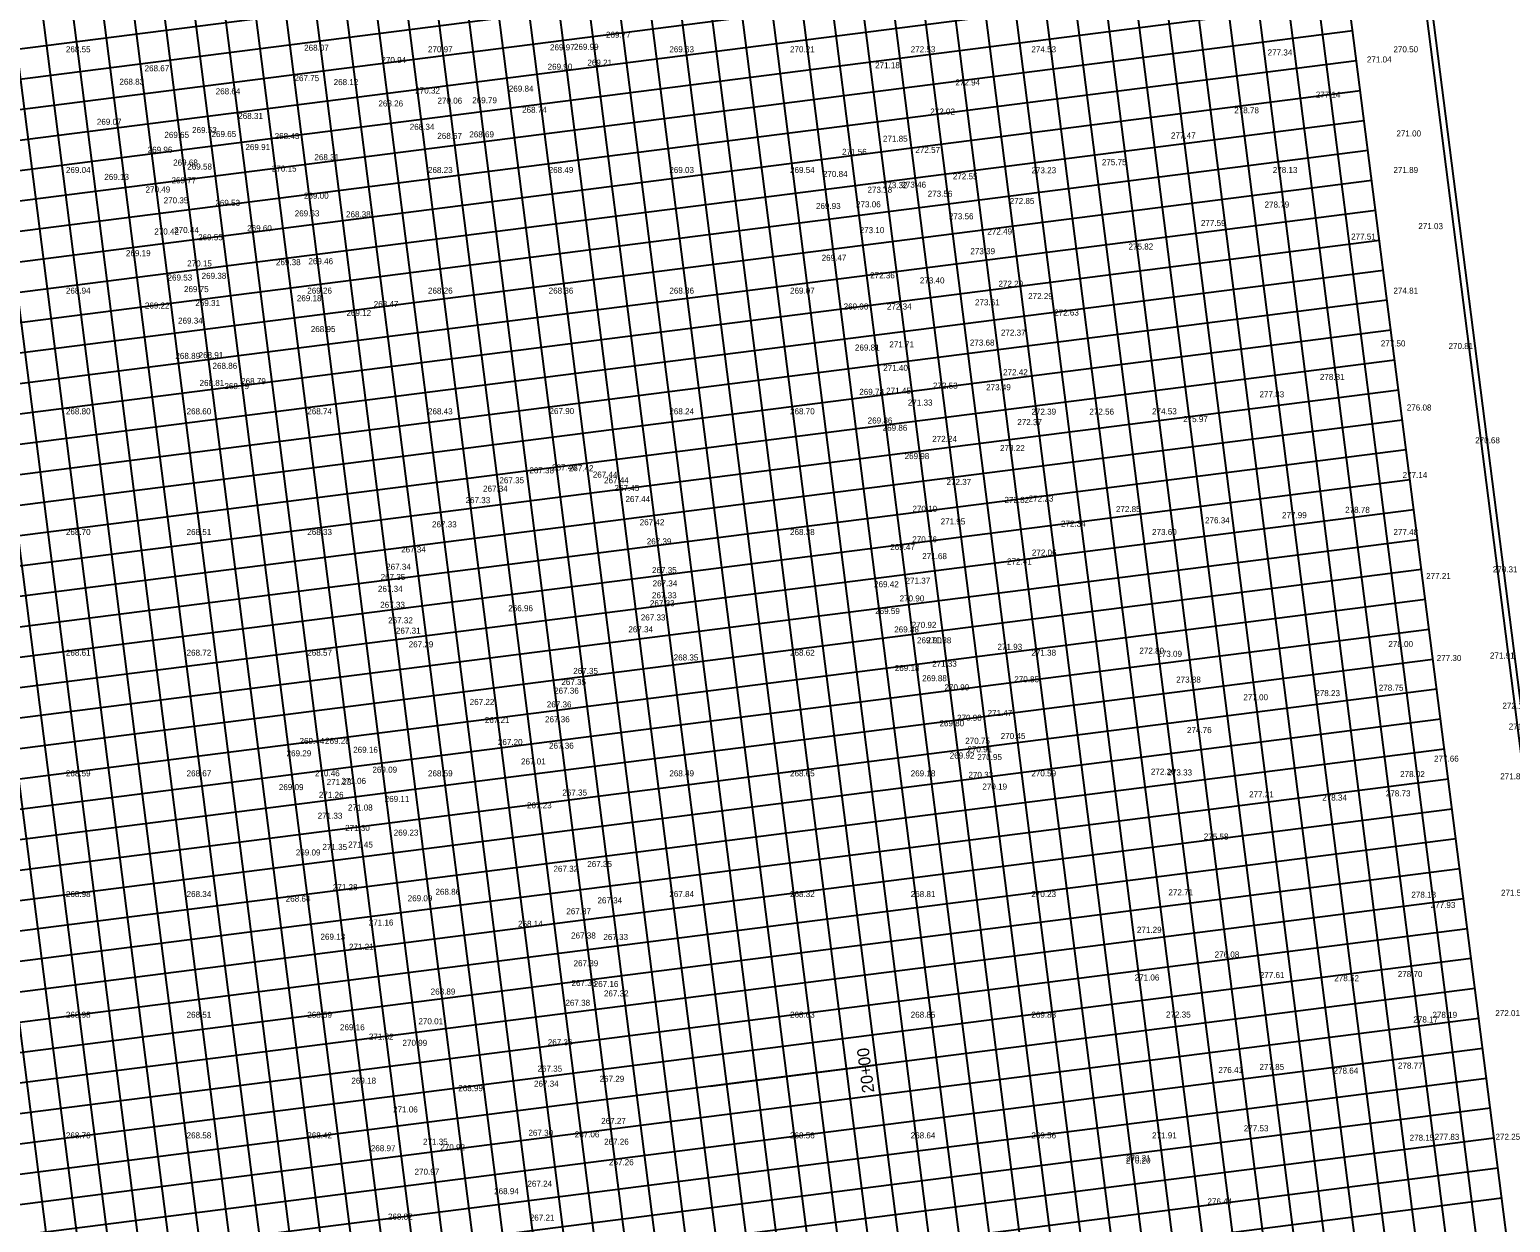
# Model space of a CAD drawing. Extents: x 2166991 to 2168450, y 842134 to 844444.
# Drawn here: x 2167887.5 to 2168132.8, y 843607.1 to 843804.8 of the extents above; entities that cross this region are included whole.
import ezdxf

# ---------------------------------------------------------------- set-up
doc = ezdxf.new("R2010")
doc.units = 0
for name, color, linetype in [('Exist Plan Preparation Drainage Notes Label', 7, 'Continuous'), ('Prop Drainage Structure Pipe Alternate 18in Label', 7, 'Continuous'), ('Prop Plan Preparation Watershed Post Construction', 7, 'Continuous'), ('Scratch_Level_3', 7, 'Continuous')]:
    doc.layers.add(name, color=color, linetype=linetype)

msp = doc.modelspace()

# ---------------------------------------------------------------- linework, layer by layer
at = {"layer": 'Exist Plan Preparation Drainage Notes Label'}
for p, q in [((2168231.53, 842827.51), (2168073.16, 844067.43)), ((2168181.94, 842821.17), (2168023.56, 844061.1)), ((2168132.34, 842814.84), (2167973.96, 844054.76)), ((2168082.74, 842808.5), (2167924.37, 844048.43)), ((2168033.15, 842802.17), (2167874.77, 844042.09)), ((2168208.53, 842849.77), (2168056.49, 844040.1)), ((2168213.49, 842850.4), (2168061.45, 844040.73)), ((2168218.45, 842851.04), (2168066.41, 844041.37)), ((2168223.41, 842851.67), (2168071.37, 844042)), ((2168188.69, 842847.24), (2168036.65, 844037.57)), ((2168193.65, 842847.87), (2168041.61, 844038.2)), ((2168198.61, 842848.5), (2168046.57, 844038.83)), ((2168203.57, 842849.14), (2168051.53, 844039.47)), ((2168168.85, 842844.7), (2168016.81, 844035.03)), ((2168173.81, 842845.34), (2168021.77, 844035.67)), ((2168183.73, 842846.6), (2168031.69, 844036.93)), ((2168149.01, 842842.17), (2167996.97, 844032.5)), ((2168153.97, 842842.8), (2168001.93, 844033.13)), ((2168158.93, 842843.44), (2168006.89, 844033.77)), ((2168163.89, 842844.07), (2168011.85, 844034.4)), ((2168134.13, 842840.27), (2167982.09, 844030.6)), ((2168139.09, 842840.9), (2167987.05, 844031.23)), ((2168144.05, 842841.54), (2167992.01, 844031.86)), ((2168114.29, 842837.73), (2167962.25, 844028.06)), ((2168119.25, 842838.37), (2167967.21, 844028.7)), ((2168124.21, 842839), (2167972.17, 844029.33)), ((2168094.45, 842835.2), (2167942.41, 844025.53)), ((2168099.41, 842835.83), (2167947.37, 844026.16)), ((2168104.37, 842836.47), (2167952.33, 844026.8)), ((2168109.33, 842837.1), (2167957.29, 844027.43)), ((2168074.61, 842832.67), (2167922.57, 844023)), ((2168084.53, 842833.93), (2167932.49, 844024.26)), ((2168089.49, 842834.57), (2167937.45, 844024.9)), ((2168054.78, 842830.13), (2167902.74, 844020.46)), ((2168059.74, 842830.77), (2167907.69, 844021.1)), ((2168064.7, 842831.4), (2167912.65, 844021.73)), ((2168069.66, 842832.03), (2167917.61, 844022.36)), ((2168034.94, 842827.6), (2167882.9, 844017.93)), ((2168039.9, 842828.23), (2167887.86, 844018.56)), ((2168044.86, 842828.87), (2167892.82, 844019.19)), ((2168049.82, 842829.5), (2167897.78, 844019.83)), ((2168015.1, 842825.06), (2167863.06, 844015.39)), ((2168020.06, 842825.7), (2167868.02, 844016.03)), ((2168025.02, 842826.33), (2167872.98, 844016.66)), ((2167995.26, 842822.53), (2167843.22, 844012.86)), ((2168000.22, 842823.16), (2167848.18, 844013.49)), ((2168005.18, 842823.8), (2167853.14, 844014.13)), ((2168010.14, 842824.43), (2167858.1, 844014.76)), ((2167990.3, 842821.9), (2167838.26, 844012.23)), ((2168103.57, 843829.37), (2167607.59, 843766.02)), ((2168104.2, 843824.41), (2167608.23, 843761.06)), ((2168104.83, 843819.45), (2167608.86, 843756.1)), ((2168105.47, 843814.49), (2167609.5, 843751.14)), ((2168106.1, 843809.53), (2167610.13, 843746.18)), ((2168106.73, 843804.57), (2167610.76, 843741.22)), ((2168107.37, 843799.61), (2167611.4, 843736.26)), ((2168108, 843794.65), (2167587.23, 843728.13)), ((2168108.63, 843789.69), (2167612.66, 843726.34)), ((2168109.27, 843784.73), (2167613.3, 843721.38)), ((2168109.9, 843779.77), (2167613.93, 843716.42)), ((2168110.53, 843774.81), (2167614.56, 843711.46)), ((2168111.17, 843769.85), (2167615.2, 843706.5)), ((2168111.8, 843764.89), (2167615.83, 843701.54)), ((2168112.43, 843759.93), (2167616.46, 843696.58)), ((2168113.07, 843754.97), (2167617.1, 843691.62)), ((2168113.7, 843750.01), (2167617.73, 843686.66)), ((2168114.34, 843745.05), (2167593.57, 843678.53)), ((2168114.97, 843740.09), (2167619, 843676.74)), ((2168115.6, 843735.13), (2167619.63, 843671.78)), ((2168116.24, 843730.17), (2167620.27, 843666.82)), ((2168116.87, 843725.21), (2167620.9, 843661.86)), ((2168117.5, 843720.25), (2167621.53, 843656.9)), ((2168118.14, 843715.29), (2167622.17, 843651.94)), ((2168118.77, 843710.33), (2167622.8, 843646.98)), ((2168119.4, 843705.37), (2167623.43, 843642.02)), ((2168120.04, 843700.41), (2167624.07, 843637.06)), ((2168120.67, 843695.46), (2167599.9, 843628.94)), ((2168121.3, 843690.5), (2167625.33, 843627.15)), ((2168121.94, 843685.54), (2167625.97, 843622.19)), ((2168122.57, 843680.58), (2167626.6, 843617.23)), ((2168123.2, 843675.62), (2167627.23, 843612.27)), ((2168123.84, 843670.66), (2167627.87, 843607.31)), ((2168124.47, 843665.7), (2167628.5, 843602.35)), ((2168125.1, 843660.74), (2167629.13, 843597.39)), ((2168125.74, 843655.78), (2167629.77, 843592.43)), ((2168126.37, 843650.82), (2167630.4, 843587.47)), ((2168127.01, 843645.86), (2167606.24, 843579.34)), ((2168127.64, 843640.9), (2167631.67, 843577.55)), ((2168128.27, 843635.94), (2167632.3, 843572.59)), ((2168128.91, 843630.98), (2167632.94, 843567.63)), ((2168129.54, 843626.02), (2167633.57, 843562.67)), ((2168130.17, 843621.06), (2167634.2, 843557.71)), ((2168130.81, 843616.1), (2167634.84, 843552.75)), ((2168131.44, 843611.14), (2167635.47, 843547.79))]:
    msp.add_line(p, q, dxfattribs=at)
msp.add_lwpolyline([(2166992.52, 843944.53), (2167154.06, 842679.8), (2168245.2, 842819.17), (2168083.66, 844083.9)], close=True, dxfattribs=at)
at = {"layer": 'Prop Drainage Structure Pipe Alternate 18in Label'}
msp.add_line((2168027.81, 843633.18), (2168000.26, 843629.66), dxfattribs=at)
at = {"layer": 'Prop Plan Preparation Watershed Post Construction'}
msp.add_lwpolyline([(2168246.32, 842818.31), (2168084.52, 844085.01), (2166991.4, 843945.39), (2167153.2, 842678.68)], close=True, dxfattribs=at)

# ---------------------------------------------------------------- texts
at = {"layer": 'Prop Drainage Structure Pipe Alternate 18in Label'}
msp.add_text('20+00', height=2, rotation=97.279, dxfattribs=at).set_placement((2168027.46, 843628.7))
at = {"layer": 'Scratch_Level_3'}
for s, p in [('269.77', (2167982.97, 843803.44)), ('268.55', (2167893.47, 843801.03)), ('268.07', (2167932.95, 843801.29)), ('270.97', (2167953.47, 843801.03)), ('269.97', (2167973.69, 843801.35)), ('269.99', (2167977.66, 843801.44)), ('269.63', (2167993.47, 843801.03)), ('270.21', (2168013.47, 843801.03)), ('272.53', (2168033.47, 843801.03)), ('274.53', (2168053.47, 843801.03)), ('270.50', (2168113.47, 843801.03)), ('270.94', (2167945.76, 843799.25)), ('269.21', (2167979.89, 843798.82)), ('271.18', (2168027.58, 843798.39)), ('277.34', (2168092.62, 843800.5)), ('271.04', (2168109.07, 843799.34)), ('268.67', (2167906.51, 843797.88)), ('267.75', (2167931.35, 843796.25)), ('269.90', (2167973.3, 843798.14)), ('268.83', (2167902.34, 843795.66)), ('268.64', (2167918.29, 843794.07)), ('268.12', (2167937.84, 843795.59)), ('270.32', (2167951.36, 843794.2)), ('269.84', (2167966.87, 843794.51)), ('272.94', (2168040.88, 843795.53)), ('277.14', (2168100.6, 843793.52)), ('268.26', (2167945.26, 843792.05)), ('270.06', (2167955.05, 843792.52)), ('269.79', (2167960.81, 843792.58)), ('268.74', (2167969.07, 843791)), ('278.78', (2168087.09, 843790.92)), ('269.07', (2167898.6, 843789.01)), ('268.31', (2167922.03, 843789.98)), ('272.02', (2168036.71, 843790.71)), ('269.65', (2167909.79, 843786.85)), ('269.53', (2167914.38, 843787.64)), ('269.65', (2167917.6, 843786.98)), ('268.43', (2167928.06, 843786.65)), ('268.34', (2167950.45, 843788.18)), ('268.57', (2167955.02, 843786.68)), ('268.69', (2167960.32, 843786.93)), ('271.85', (2168028.87, 843786.21)), ('277.47', (2168076.6, 843786.74)), ('271.00', (2168113.96, 843787.08)), ('269.96', (2167907.02, 843784.38)), ('269.91', (2167923.22, 843784.82)), ('271.56', (2168022.1, 843784.03)), ('272.57', (2168034.25, 843784.35)), ('269.68', (2167911.24, 843782.26)), ('269.58', (2167913.58, 843781.59)), ('270.15', (2167927.6, 843781.26)), ('268.31', (2167934.65, 843783.15)), ('275.75', (2168065.15, 843782.32)), ('269.04', (2167893.47, 843781.03)), ('269.13', (2167899.83, 843779.88)), ('269.77', (2167910.97, 843779.32)), ('268.23', (2167953.47, 843781.03)), ('268.49', (2167973.47, 843781.03)), ('269.03', (2167993.47, 843781.03)), ('269.54', (2168013.47, 843781.03)), ('270.84', (2168018.92, 843780.37)), ('272.55', (2168040.45, 843779.97)), ('273.23', (2168053.48, 843780.98)), ('278.13', (2168093.47, 843781.03)), ('271.89', (2168113.47, 843781.03)), ('270.49', (2167906.67, 843777.79)), ('269.00', (2167932.92, 843776.76)), ('273.18', (2168026.31, 843777.75)), ('273.32', (2168028.85, 843778.51)), ('273.46', (2168031.93, 843778.59)), ('273.56', (2168036.29, 843777.09)), ('270.35', (2167909.67, 843775.99)), ('269.53', (2167918.24, 843775.58)), ('269.63', (2167931.39, 843773.83)), ('269.93', (2168017.77, 843775.06)), ('273.06', (2168024.41, 843775.34)), ('272.85', (2168049.88, 843775.89)), ('278.79', (2168092.11, 843775.3)), ('269.60', (2167923.51, 843771.38)), ('268.38', (2167939.89, 843773.69)), ('273.56', (2168039.79, 843773.35)), ('277.59', (2168081.56, 843772.24)), ('271.03', (2168117.59, 843771.72)), ('270.42', (2167908.12, 843770.83)), ('270.44', (2167911.41, 843771.07)), ('269.55', (2167915.38, 843769.88)), ('273.10', (2168025.01, 843771.06)), ('272.49', (2168046.18, 843770.83)), ('277.51', (2168106.46, 843769.99)), ('269.19', (2167903.42, 843767.24)), ('269.47', (2168018.71, 843766.48)), ('273.39', (2168043.36, 843767.57)), ('275.82', (2168069.57, 843768.34)), ('270.15', (2167913.57, 843765.54)), ('269.38', (2167928.28, 843765.75)), ('269.46', (2167933.66, 843765.91)), ('269.53', (2167910.31, 843763.2)), ('269.38', (2167915.96, 843763.48)), ('272.36', (2168026.75, 843763.56)), ('273.40', (2168034.99, 843762.72)), ('272.29', (2168048.01, 843762.17)), ('268.94', (2167893.47, 843761.03)), ('269.75', (2167913.04, 843761.28)), ('269.18', (2167931.74, 843759.78)), ('269.26', (2167933.47, 843761.03)), ('268.26', (2167953.47, 843761.03)), ('268.36', (2167973.47, 843761.03)), ('268.86', (2167993.47, 843761.03)), ('269.07', (2168013.47, 843761.03)), ('273.61', (2168044.12, 843759.09)), ('272.29', (2168052.93, 843760.12)), ('274.81', (2168113.47, 843761.03)), ('269.22', (2167906.56, 843758.56)), ('269.31', (2167914.92, 843758.97)), ('269.12', (2167939.96, 843757.33)), ('268.47', (2167944.48, 843758.8)), ('269.90', (2168022.36, 843758.4)), ('272.34', (2168029.53, 843758.4)), ('272.63', (2168057.25, 843757.4)), ('269.34', (2167912.06, 843756.06)), ('268.95', (2167934.05, 843754.66)), ('271.71', (2168029.93, 843752.11)), ('273.68', (2168043.27, 843752.42)), ('272.37', (2168048.42, 843754.07)), ('277.50', (2168111.37, 843752.28)), ('270.81', (2168122.6, 843751.85)), ('268.89', (2167911.62, 843750.22)), ('268.91', (2167915.46, 843750.34)), ('269.81', (2168024.23, 843751.6)), ('268.86', (2167917.77, 843748.57)), ('271.40', (2168028.92, 843748.23)), ('272.42', (2168048.78, 843747.51)), ('278.81', (2168101.28, 843746.73)), ('268.81', (2167915.62, 843745.74)), ('268.79', (2167919.73, 843745.21)), ('268.79', (2167922.51, 843746.03)), ('271.45', (2168029.4, 843744.43)), ('272.53', (2168037.16, 843745.29)), ('273.49', (2168045.97, 843745.02)), ('269.78', (2168024.95, 843744.26)), ('271.33', (2168033, 843742.48)), ('277.83', (2168091.27, 843743.86)), ('268.80', (2167893.47, 843741.03)), ('268.60', (2167913.47, 843741.03)), ('268.74', (2167933.47, 843741.03)), ('268.43', (2167953.47, 843741.03)), ('267.90', (2167973.61, 843741.07)), ('268.24', (2167993.47, 843741.03)), ('268.70', (2168013.47, 843741.03)), ('269.86', (2168026.34, 843739.51)), ('272.39', (2168053.48, 843740.98)), ('272.56', (2168063.08, 843740.98)), ('274.53', (2168073.47, 843741.03)), ('275.97', (2168078.62, 843739.74)), ('276.08', (2168115.68, 843741.66)), ('269.86', (2168028.82, 843738.3)), ('272.37', (2168051.13, 843739.24)), ('272.24', (2168037.04, 843736.46)), ('273.22', (2168048.28, 843734.94)), ('270.68', (2168127.02, 843736.23)), ('269.98', (2168032.46, 843733.61)), ('267.35', (2167965.31, 843729.61)), ('267.38', (2167970.27, 843731.25)), ('267.40', (2167974.03, 843731.73)), ('267.42', (2167976.81, 843731.61)), ('267.44', (2167980.79, 843730.55)), ('267.44', (2167982.65, 843729.6)), ('277.14', (2168114.99, 843730.48)), ('267.34', (2167962.6, 843728.22)), ('267.45', (2167984.39, 843728.33)), ('272.37', (2168039.41, 843729.33)), ('267.33', (2167959.7, 843726.31)), ('267.44', (2167986.2, 843726.49)), ('270.10', (2168033.76, 843724.87)), ('272.82', (2168049.01, 843726.35)), ('272.23', (2168053.03, 843726.57)), ('272.85', (2168067.48, 843724.83)), ('278.78', (2168105.46, 843724.7)), ('267.33', (2167954.14, 843722.3)), ('267.42', (2167988.56, 843722.65)), ('271.95', (2168038.43, 843722.78)), ('272.34', (2168058.37, 843722.41)), ('276.34', (2168082.25, 843722.97)), ('277.99', (2168095.01, 843723.82)), ('268.70', (2167893.47, 843721.03)), ('268.51', (2167913.47, 843721.03)), ('268.33', (2167933.47, 843721.03)), ('268.38', (2168013.47, 843721.03)), ('270.76', (2168033.73, 843719.81)), ('273.60', (2168073.47, 843721.03)), ('277.48', (2168113.47, 843721.03)), ('267.34', (2167949.02, 843718.14)), ('267.39', (2167989.73, 843719.47)), ('269.47', (2168030.08, 843718.54)), ('272.06', (2168053.55, 843717.62)), ('267.34', (2167946.54, 843715.27)), ('271.68', (2168035.38, 843717.03)), ('272.41', (2168049.44, 843716.14)), ('270.31', (2168129.94, 843714.84)), ('267.35', (2167945.63, 843713.58)), ('267.35', (2167990.6, 843714.71)), ('267.34', (2167990.7, 843712.51)), ('269.42', (2168027.4, 843712.38)), ('271.37', (2168032.62, 843712.96)), ('277.21', (2168118.89, 843713.74)), ('267.34', (2167945.18, 843711.61)), ('267.33', (2167990.59, 843710.54)), ('270.90', (2168031.63, 843710.02)), ('267.33', (2167945.56, 843708.97)), ('266.96', (2167966.78, 843708.4)), ('267.33', (2167990.25, 843709.23)), ('269.59', (2168027.58, 843707.93)), ('267.32', (2167946.87, 843706.39)), ('267.33', (2167988.74, 843706.87)), ('270.92', (2168033.64, 843705.64)), ('267.31', (2167948.16, 843704.68)), ('267.34', (2167986.68, 843704.9)), ('269.88', (2168030.74, 843704.88)), ('269.90', (2168034.51, 843703.08)), ('271.38', (2168036.11, 843703.08)), ('268.61', (2167893.47, 843701.03)), ('268.72', (2167913.47, 843701.03)), ('268.57', (2167933.47, 843701.03)), ('267.29', (2167950.27, 843702.41)), ('268.35', (2167994.19, 843700.24)), ('268.62', (2168013.47, 843701.03)), ('271.93', (2168047.85, 843702)), ('271.38', (2168053.47, 843701.03)), ('272.80', (2168071.37, 843701.35)), ('273.09', (2168074.34, 843700.84)), ('278.00', (2168112.63, 843702.46)), ('277.30', (2168120.64, 843700.15)), ('271.91', (2168129.46, 843700.56)), ('267.35', (2167977.55, 843698.01)), ('269.18', (2168030.83, 843698.49)), ('271.33', (2168037.02, 843699.19)), ('267.35', (2167975.58, 843696.17)), ('269.88', (2168035.37, 843696.8)), ('270.90', (2168039.07, 843695.28)), ('270.85', (2168050.64, 843696.63)), ('273.88', (2168077.46, 843696.57)), ('278.75', (2168111.04, 843695.23)), ('267.22', (2167960.39, 843692.87)), ('267.36', (2167974.38, 843694.74)), ('277.00', (2168088.6, 843693.65)), ('278.23', (2168100.52, 843694.33)), ('267.36', (2167973.17, 843692.46)), ('271.47', (2168046.21, 843691.04)), ('272.11', (2168131.53, 843692.24)), ('267.21', (2167962.9, 843689.87)), ('267.36', (2167972.87, 843690)), ('269.80', (2168038.24, 843689.33)), ('270.90', (2168041.15, 843690.24)), ('274.76', (2168079.25, 843688.2)), ('271.60', (2168132.58, 843688.79)), ('269.44', (2167932.19, 843686.4)), ('269.28', (2167936.42, 843686.42)), ('267.20', (2167965.06, 843686.22)), ('267.36', (2167973.54, 843685.62)), ('270.75', (2168042.51, 843686.42)), ('270.45', (2168048.39, 843687.22)), ('269.29', (2167930.04, 843684.35)), ('269.16', (2167941.08, 843684.94)), ('267.01', (2167968.89, 843683)), ('269.92', (2168039.94, 843683.99)), ('270.91', (2168042.87, 843685.01)), ('270.95', (2168044.5, 843683.73)), ('277.66', (2168120.2, 843683.47)), ('268.59', (2167893.47, 843681.03)), ('268.67', (2167913.47, 843681.03)), ('270.46', (2167934.75, 843681.05)), ('269.09', (2167944.27, 843681.64)), ('268.59', (2167953.47, 843681.03)), ('268.49', (2167993.47, 843681.03)), ('268.65', (2168013.47, 843681.03)), ('269.18', (2168033.47, 843681.03)), ('270.33', (2168043.04, 843680.78)), ('270.59', (2168053.47, 843681.03)), ('272.20', (2168073.27, 843681.32)), ('273.33', (2168076.01, 843681.18)), ('278.02', (2168114.58, 843680.91)), ('271.89', (2168131.17, 843680.54)), ('269.09', (2167928.76, 843678.75)), ('271.23', (2167936.69, 843679.61)), ('271.06', (2167939.12, 843679.78)), ('270.19', (2168045.35, 843678.84)), ('271.26', (2167935.39, 843677.47)), ('269.11', (2167946.3, 843676.8)), ('267.23', (2167969.88, 843675.74)), ('267.35', (2167975.74, 843677.85)), ('277.21', (2168089.55, 843677.56)), ('278.34', (2168101.67, 843677.02)), ('278.73', (2168112.21, 843677.71)), ('271.33', (2167935.2, 843674.01)), ('271.08', (2167940.22, 843675.37)), ('271.30', (2167939.75, 843671.99)), ('269.23', (2167947.8, 843671.21)), ('271.35', (2167935.98, 843668.84)), ('271.45', (2167940.25, 843669.23)), ('275.58', (2168082.04, 843670.56)), ('269.09', (2167931.57, 843667.92)), ('267.35', (2167979.87, 843666)), ('267.32', (2167974.27, 843665.21)), ('268.98', (2167893.47, 843661.03)), ('268.34', (2167913.47, 843661.03)), ('271.28', (2167937.71, 843662.17)), ('268.86', (2167954.71, 843661.41)), ('267.84', (2167993.47, 843661.03)), ('268.32', (2168013.47, 843661.03)), ('268.81', (2168033.47, 843661.03)), ('270.23', (2168053.47, 843661.03)), ('272.71', (2168076.18, 843661.32)), ('278.18', (2168116.44, 843660.92)), ('271.52', (2168131.3, 843661.24)), ('268.64', (2167929.9, 843660.26)), ('269.09', (2167950.11, 843660.33)), ('267.34', (2167981.56, 843659.98)), ('277.93', (2168119.64, 843659.22)), ('271.16', (2167943.66, 843656.31)), ('268.14', (2167968.4, 843656.1)), ('267.37', (2167976.4, 843658.18)), ('269.13', (2167935.66, 843653.96)), ('267.38', (2167977.19, 843654.16)), ('267.33', (2167982.54, 843653.92)), ('271.29', (2168070.96, 843655.1)), ('271.21', (2167940.38, 843652.29)), ('276.08', (2168083.84, 843651.01)), ('267.39', (2167977.6, 843649.56)), ('267.38', (2167977.26, 843646.29)), ('267.16', (2167980.94, 843646.12)), ('271.06', (2168070.59, 843647.2)), ('277.61', (2168091.32, 843647.61)), ('278.52', (2168103.67, 843647.09)), ('278.70', (2168114.19, 843647.77)), ('268.89', (2167953.92, 843644.87)), ('267.32', (2167982.63, 843644.56)), ('267.38', (2167976.25, 843643.01)), ('272.01', (2168130.35, 843641.3)), ('268.98', (2167893.47, 843641.03)), ('268.51', (2167913.47, 843641.03)), ('268.59', (2167933.47, 843641.03)), ('269.16', (2167938.89, 843638.95)), ('270.01', (2167951.89, 843639.95)), ('268.63', (2168013.47, 843641.03)), ('268.85', (2168033.47, 843641.03)), ('269.83', (2168053.47, 843641.03)), ('272.35', (2168075.78, 843641.06)), ('278.17', (2168116.77, 843640.24)), ('278.19', (2168119.93, 843641.01)), ('271.32', (2167943.68, 843637.4)), ('270.99', (2167949.25, 843636.37)), ('267.36', (2167973.33, 843636.47)), ('267.35', (2167971.62, 843632.1)), ('276.41', (2168084.45, 843631.87)), ('277.85', (2168091.27, 843632.38)), ('278.64', (2168103.54, 843631.77)), ('278.77', (2168114.22, 843632.6)), ('269.18', (2167940.78, 843630.1)), ('267.34', (2167971.04, 843629.6)), ('267.29', (2167981.91, 843630.41)), ('268.99', (2167958.49, 843628.86)), ('271.06', (2167947.69, 843625.33)), ('267.27', (2167982.18, 843623.43)), ('277.53', (2168088.67, 843622.21)), ('268.76', (2167893.47, 843621.03)), ('268.58', (2167913.47, 843621.03)), ('268.42', (2167933.47, 843621.03)), ('271.35', (2167952.65, 843619.99)), ('267.30', (2167970.12, 843621.46)), ('267.06', (2167977.79, 843621.2)), ('267.26', (2167982.66, 843619.99)), ('268.56', (2168013.47, 843621.03)), ('268.64', (2168033.47, 843621.03)), ('269.56', (2168053.47, 843621.03)), ('271.91', (2168073.47, 843621.03)), ('278.15', (2168116.15, 843620.64)), ('277.83', (2168120.3, 843620.79)), ('272.25', (2168130.38, 843620.8)), ('268.97', (2167944, 843618.91)), ('270.92', (2167955.52, 843619.07)), ('270.20', (2168069.13, 843616.87)), ('270.21', (2168069.15, 843617.25)), ('270.97', (2167951.25, 843615.01)), ('267.26', (2167983.47, 843616.59)), ('268.94', (2167964.44, 843611.79)), ('267.24', (2167969.95, 843613.02)), ('276.44', (2168082.65, 843610.09)), ('268.82', (2167946.84, 843607.57)), ('267.21', (2167970.35, 843607.41))]:
    msp.add_text(s, height=1, dxfattribs=at).set_placement(p)

doc.saveas('drawing.dxf')
